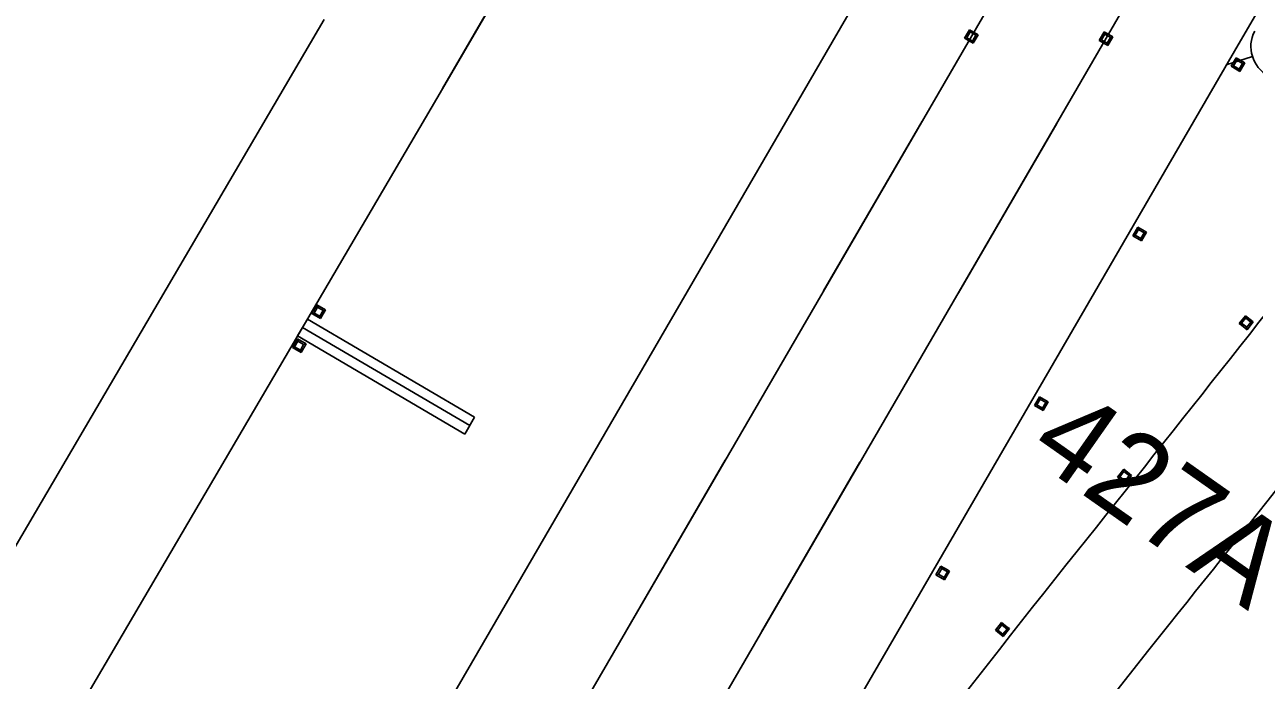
# Model space of a CAD drawing. Extents: x 2471014 to 2497726, y 6959577 to 6980268.
# Drawn here: x 2488611.6 to 2488737.2, y 6964325 to 6964391.9 of the extents above; entities that cross this region are included whole.
import ezdxf

# ---------------------------------------------------------------- set-up
doc = ezdxf.new("R2010")
doc.units = 0
for name, color, linetype in [('13', 7, 'Continuous'), ('18', 7, 'Continuous'), ('23', 7, 'Continuous'), ('25', 7, 'Continuous'), ('5', 7, 'Continuous'), ('G-GRID-MAJR', 7, 'Continuous'), ('Level 30', 7, 'Continuous'), ('PMK_Pav_Mark_Wht_Number', 7, 'Continuous'), ('PMK_Pav_Marker_TY I C', 7, 'Continuous'), ('RDWY_PAVE_XSTREET_FOC', 7, 'Continuous'), ('S-BRDG-DECK', 7, 'Continuous'), ('V7_25', 7, 'Continuous')]:
    doc.layers.add(name, color=color, linetype=linetype)

msp = doc.modelspace()

# ---------------------------------------------------------------- linework, layer by layer
at = {"layer": '13'}
msp.add_line((2488620.75, 6964263.98), (2489501.89, 6965780.24), dxfattribs=at)
at = {"layer": '18'}
for p, q in [((2488735.14, 6964389.16), (2489533.02, 6965762.15)), ((2488654.28, 6964385.36), (2488737.13, 6964527.93)), ((2488581.52, 6964289.01), (2488642.18, 6964392.39)), ((2488593.6, 6964281.93), (2488654.25, 6964385.31))]:
    msp.add_line(p, q, dxfattribs=at)
msp.add_arc((2489916.91, 6963512.7), 1400, 142.23979, 191.359, dxfattribs=at)
at = {"layer": '23'}
for p, q in [((2488707.57, 6964390.48), (2488708.08, 6964391.35)), ((2488707.79, 6964390.54), (2488707.57, 6964390.48)), ((2488707.57, 6964390.48), (2488707.8, 6964390.34)), ((2488708.38, 6964390.2), (2488707.79, 6964390.54)), ((2488707.8, 6964390.34), (2488708.45, 6964389.97)), ((2488708.96, 6964390.84), (2488708.08, 6964391.35)), ((2488708.08, 6964391.35), (2488708.13, 6964391.13)), ((2488708.13, 6964391.13), (2488708.25, 6964391.06)), ((2488708.25, 6964391.06), (2488708.72, 6964390.79)), ((2488708.45, 6964389.97), (2488708.38, 6964390.2)), ((2488708.96, 6964390.84), (2488708.45, 6964389.97)), ((2488708.72, 6964390.79), (2488708.96, 6964390.84)), ((2488721.32, 6964390.26), (2488721.83, 6964391.14)), ((2488721.55, 6964390.33), (2488721.32, 6964390.26)), ((2488721.32, 6964390.26), (2488721.56, 6964390.13)), ((2488722.13, 6964389.99), (2488721.55, 6964390.33)), ((2488721.56, 6964390.13), (2488722.2, 6964389.75)), ((2488722.71, 6964390.63), (2488721.83, 6964391.14)), ((2488721.83, 6964391.14), (2488721.89, 6964390.91)), ((2488721.89, 6964390.91), (2488722.01, 6964390.84)), ((2488722.01, 6964390.84), (2488722.47, 6964390.57)), ((2488722.71, 6964390.63), (2488722.2, 6964389.75)), ((2488722.47, 6964390.57), (2488722.71, 6964390.63)), ((2488722.2, 6964389.75), (2488722.13, 6964389.99)), ((2488734.8, 6964387.62), (2488735.31, 6964388.49)), ((2488735.04, 6964387.67), (2488734.8, 6964387.62)), ((2488734.8, 6964387.62), (2488735.68, 6964387.1)), ((2488735.5, 6964387.4), (2488735.04, 6964387.67)), ((2488735.95, 6964388.12), (2488735.31, 6964388.49)), ((2488735.31, 6964388.49), (2488735.38, 6964388.26)), ((2488735.38, 6964388.26), (2488735.96, 6964387.92)), ((2488736.19, 6964387.98), (2488735.68, 6964387.1)), ((2488736.19, 6964387.98), (2488735.95, 6964388.12)), ((2488735.96, 6964387.92), (2488736.19, 6964387.98)), ((2488735.62, 6964387.33), (2488735.5, 6964387.4)), ((2488735.68, 6964387.1), (2488735.62, 6964387.33)), ((2488724.75, 6964370.32), (2488725.26, 6964371.2)), ((2488724.99, 6964370.38), (2488724.75, 6964370.32)), ((2488724.75, 6964370.32), (2488725.63, 6964369.81)), ((2488725.45, 6964370.11), (2488724.99, 6964370.38)), ((2488725.9, 6964370.83), (2488725.26, 6964371.2)), ((2488725.26, 6964371.2), (2488725.33, 6964370.97)), ((2488725.33, 6964370.97), (2488725.91, 6964370.63)), ((2488725.57, 6964370.04), (2488725.45, 6964370.11)), ((2488725.63, 6964369.81), (2488725.57, 6964370.04)), ((2488726.14, 6964370.69), (2488725.63, 6964369.81)), ((2488726.14, 6964370.69), (2488725.9, 6964370.83)), ((2488725.91, 6964370.63), (2488726.14, 6964370.69)), ((2488735.62, 6964361.38), (2488736.25, 6964362.18)), ((2488735.85, 6964361.42), (2488735.62, 6964361.38)), ((2488735.62, 6964361.38), (2488735.83, 6964361.22)), ((2488736.38, 6964361), (2488735.85, 6964361.42)), ((2488737.04, 6964361.55), (2488736.25, 6964362.18)), ((2488736.25, 6964362.18), (2488736.27, 6964361.95)), ((2488736.27, 6964361.95), (2488736.38, 6964361.86)), ((2488736.38, 6964361.86), (2488736.8, 6964361.53)), ((2488737.04, 6964361.55), (2488736.41, 6964360.75)), ((2488736.8, 6964361.53), (2488737.04, 6964361.55)), ((2488735.83, 6964361.22), (2488736.41, 6964360.75)), ((2488736.41, 6964360.75), (2488736.38, 6964361)), ((2488714.7, 6964353.03), (2488715.21, 6964353.91)), ((2488715.85, 6964353.53), (2488715.21, 6964353.91)), ((2488715.21, 6964353.91), (2488715.28, 6964353.67)), ((2488714.94, 6964353.09), (2488714.7, 6964353.03)), ((2488714.7, 6964353.03), (2488715.58, 6964352.52)), ((2488715.4, 6964352.82), (2488714.94, 6964353.09)), ((2488715.28, 6964353.67), (2488715.87, 6964353.33)), ((2488715.53, 6964352.75), (2488715.4, 6964352.82)), ((2488715.58, 6964352.52), (2488715.53, 6964352.75)), ((2488716.09, 6964353.4), (2488715.58, 6964352.52)), ((2488716.09, 6964353.4), (2488715.85, 6964353.53)), ((2488715.87, 6964353.33), (2488716.09, 6964353.4)), ((2488723.19, 6964345.72), (2488723.82, 6964346.51)), ((2488724.61, 6964345.88), (2488723.82, 6964346.51)), ((2488723.82, 6964346.51), (2488723.84, 6964346.28)), ((2488723.84, 6964346.28), (2488723.95, 6964346.19)), ((2488723.95, 6964346.19), (2488724.37, 6964345.86)), ((2488723.42, 6964345.75), (2488723.19, 6964345.72)), ((2488723.19, 6964345.72), (2488723.4, 6964345.55)), ((2488723.4, 6964345.55), (2488723.98, 6964345.08)), ((2488723.95, 6964345.33), (2488723.42, 6964345.75)), ((2488723.98, 6964345.08), (2488723.95, 6964345.33)), ((2488724.61, 6964345.88), (2488723.98, 6964345.08)), ((2488724.37, 6964345.86), (2488724.61, 6964345.88)), ((2488704.65, 6964335.74), (2488705.16, 6964336.62)), ((2488705.81, 6964336.24), (2488705.16, 6964336.62)), ((2488705.16, 6964336.62), (2488705.23, 6964336.38)), ((2488705.23, 6964336.38), (2488705.82, 6964336.04)), ((2488706.04, 6964336.11), (2488705.81, 6964336.24)), ((2488704.89, 6964335.8), (2488704.65, 6964335.74)), ((2488704.65, 6964335.74), (2488705.53, 6964335.23)), ((2488705.35, 6964335.53), (2488704.89, 6964335.8)), ((2488705.48, 6964335.46), (2488705.35, 6964335.53)), ((2488705.53, 6964335.23), (2488705.48, 6964335.46)), ((2488706.04, 6964336.11), (2488705.53, 6964335.23)), ((2488705.82, 6964336.04), (2488706.04, 6964336.11)), ((2488710.72, 6964330.08), (2488711.34, 6964330.87)), ((2488710.96, 6964330.1), (2488710.72, 6964330.08)), ((2488710.72, 6964330.08), (2488711.51, 6964329.45)), ((2488711.38, 6964329.77), (2488710.96, 6964330.1)), ((2488711.93, 6964330.41), (2488711.34, 6964330.87)), ((2488711.34, 6964330.87), (2488711.38, 6964330.63)), ((2488711.38, 6964330.63), (2488711.91, 6964330.21)), ((2488712.14, 6964330.25), (2488711.51, 6964329.45)), ((2488711.91, 6964330.21), (2488712.14, 6964330.25)), ((2488712.14, 6964330.25), (2488711.93, 6964330.41)), ((2488711.49, 6964329.68), (2488711.38, 6964329.77)), ((2488711.51, 6964329.45), (2488711.49, 6964329.68))]:
    msp.add_line(p, q, dxfattribs=at)
for points in [[(2488707.79, 6964390.54), (2488708.13, 6964391.13), (2488708.72, 6964390.79), (2488708.38, 6964390.2)], [(2488721.55, 6964390.33), (2488721.89, 6964390.91), (2488722.47, 6964390.57), (2488722.13, 6964389.99)], [(2488735.96, 6964387.92), (2488735.62, 6964387.33), (2488735.04, 6964387.67), (2488735.38, 6964388.26)], [(2488725.91, 6964370.63), (2488725.57, 6964370.04), (2488724.99, 6964370.38), (2488725.33, 6964370.97)], [(2488735.85, 6964361.42), (2488736.27, 6964361.95), (2488736.8, 6964361.53), (2488736.38, 6964361)], [(2488715.87, 6964353.33), (2488715.53, 6964352.75), (2488714.94, 6964353.09), (2488715.28, 6964353.67)], [(2488723.42, 6964345.75), (2488723.84, 6964346.28), (2488724.37, 6964345.86), (2488723.95, 6964345.33)], [(2488705.82, 6964336.04), (2488705.48, 6964335.46), (2488704.89, 6964335.8), (2488705.23, 6964336.38)], [(2488711.91, 6964330.21), (2488711.49, 6964329.68), (2488710.96, 6964330.1), (2488711.38, 6964330.63)]]:
    msp.add_lwpolyline(points, close=True, dxfattribs=at)
at = {"layer": '25'}
msp.add_line((2488650.61, 6964243.7), (2488735.14, 6964389.16), dxfattribs=at)
for centre, radius, start, end in [((2489916.91, 6963512.7), 1414, 142.23979, 154.2029), ((2485597.1, 6966838.82), 4000, 321.30547, 322.02534), ((2489663.45, 6963581.69), 1210, 141.30547, 146.83097)]:
    msp.add_arc(centre, radius, start, end, dxfattribs=at)
at = {"layer": '5'}
for centre, radius, start, end in [((2485597.1, 6966838.82), 4012, 321.30547, 321.97116), ((2489663.45, 6963581.69), 1198, 141.30547, 161.17883)]:
    msp.add_arc(centre, radius, start, end, dxfattribs=at)
at = {"layer": 'G-GRID-MAJR'}
for p, q in [((2488640.48, 6964361.83), (2488639.47, 6964360.11)), ((2488657.54, 6964351.82), (2488640.48, 6964361.83)), ((2488639.47, 6964360.11), (2488656.53, 6964350.09)), ((2488656.53, 6964350.09), (2488657.54, 6964351.82))]:
    msp.add_line(p, q, dxfattribs=at)
at = {"layer": 'Level 30'}
msp.add_line((2488736.95, 6964388.63), (2488734.27, 6964387.77), dxfattribs=at)
msp.add_arc((2488740.17, 6964389.63), 3.37, 152.0959, 332.0959, dxfattribs=at)
at = {"layer": 'PMK_Pav_Marker_TY I C'}
for p, q in [((2488640.94, 6964362.39), (2488641.45, 6964363.27)), ((2488642.32, 6964362.76), (2488641.45, 6964363.27)), ((2488641.45, 6964363.27), (2488641.5, 6964363.04)), ((2488641.5, 6964363.04), (2488641.62, 6964362.97)), ((2488641.62, 6964362.97), (2488642.09, 6964362.7)), ((2488642.32, 6964362.76), (2488641.82, 6964361.88)), ((2488642.09, 6964362.7), (2488642.32, 6964362.76)), ((2488641.16, 6964362.45), (2488640.94, 6964362.39)), ((2488640.94, 6964362.39), (2488641.17, 6964362.26)), ((2488641.75, 6964362.12), (2488641.16, 6964362.45)), ((2488641.17, 6964362.26), (2488641.82, 6964361.88)), ((2488641.82, 6964361.88), (2488641.75, 6964362.12)), ((2488638.94, 6964358.92), (2488639.45, 6964359.8)), ((2488639.17, 6964358.99), (2488638.94, 6964358.92)), ((2488638.94, 6964358.92), (2488639.18, 6964358.79)), ((2488639.75, 6964358.65), (2488639.17, 6964358.99)), ((2488639.18, 6964358.79), (2488639.82, 6964358.42)), ((2488640.33, 6964359.3), (2488639.45, 6964359.8)), ((2488639.45, 6964359.8), (2488639.5, 6964359.58)), ((2488639.5, 6964359.58), (2488639.63, 6964359.5)), ((2488639.63, 6964359.5), (2488640.09, 6964359.24)), ((2488640.33, 6964359.3), (2488639.82, 6964358.42)), ((2488640.09, 6964359.24), (2488640.33, 6964359.3)), ((2488639.82, 6964358.42), (2488639.75, 6964358.65))]:
    msp.add_line(p, q, dxfattribs=at)
for points in [[(2488641.16, 6964362.45), (2488641.5, 6964363.04), (2488642.09, 6964362.7), (2488641.75, 6964362.12)], [(2488639.17, 6964358.99), (2488639.5, 6964359.58), (2488640.09, 6964359.24), (2488639.75, 6964358.65)]]:
    msp.add_lwpolyline(points, close=True, dxfattribs=at)
at = {"layer": 'RDWY_PAVE_XSTREET_FOC'}
for p, q in [((2488693.18, 6964364.73), (2488703.23, 6964382.02)), ((2488706.94, 6964364.51), (2488716.98, 6964381.8)), ((2488673.08, 6964330.14), (2488683.13, 6964347.43)), ((2488686.84, 6964329.93), (2488696.89, 6964347.22))]:
    msp.add_line(p, q, dxfattribs=at)
at = {"layer": 'S-BRDG-DECK'}
for p, q in [((2488654.27, 6964385.33), (2488737.13, 6964527.93)), ((2488597.93, 6964289.32), (2488654.27, 6964385.33)), ((2488657.04, 6964350.96), (2488639.97, 6964360.97))]:
    msp.add_line(p, q, dxfattribs=at)
at = {"layer": 'V7_25'}
for p, q in [((2488631.13, 6964257.95), (2489512.27, 6965774.21)), ((2488641.5, 6964251.92), (2489522.64, 6965768.18))]:
    msp.add_line(p, q, dxfattribs=at)

# ---------------------------------------------------------------- texts
at = {"layer": 'PMK_Pav_Mark_Wht_Number'}
msp.add_text('427A', height=8.9, rotation=324.8945, dxfattribs=at).set_placement((2488713.81, 6964348))

doc.saveas('drawing.dxf')
